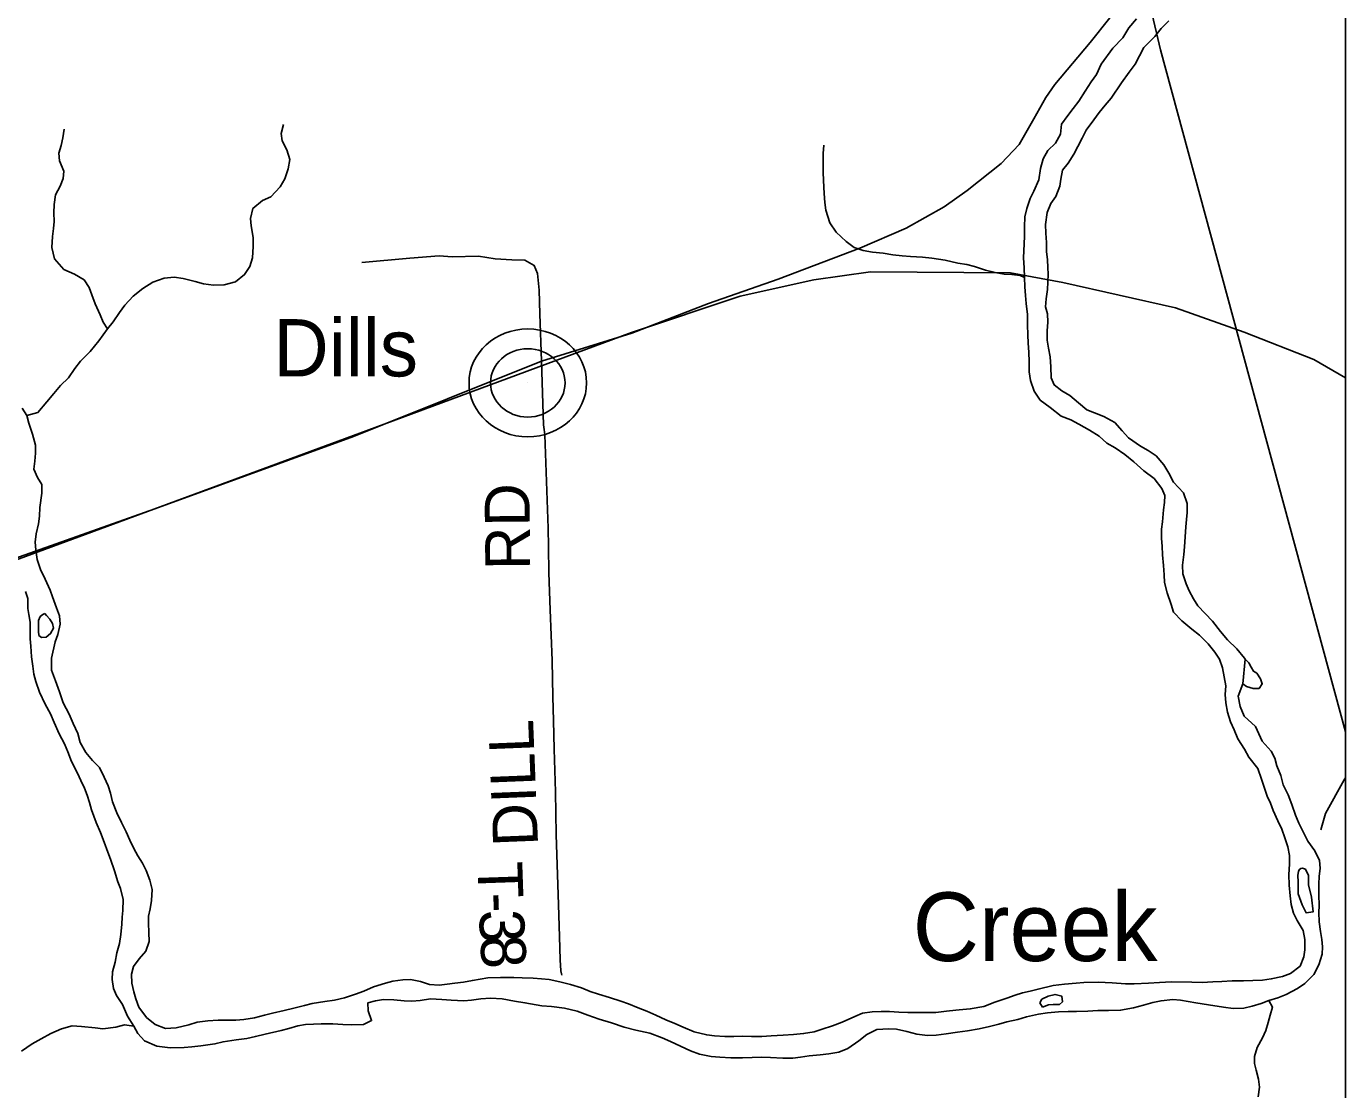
# Model space of a CAD drawing. Extents: x -139 to 835, y 0 to 440.
# Drawn here: x 550 to 607.6, y 298.1 to 344.5 of the extents above; entities that cross this region are included whole.
import ezdxf

# ---------------------------------------------------------------- set-up
doc = ezdxf.new("R2010")
doc.units = 0
for name, color, linetype in [('Default', 7, 'Continuous'), ('GM_X_Major_River', 7, 'Continuous'), ('GM_X_Major_River_Text', 7, 'Continuous'), ('GM_X_Minor_River', 7, 'Continuous'), ('GM_X_Rail_Line', 7, 'Continuous'), ('GM_X_Township_Road', 7, 'Continuous'), ('GM_X_Township_Road_Text', 7, 'Continuous'), ('GM_X_Unincorporated', 7, 'Continuous'), ('GM_X_Unincorporated_Location', 7, 'Continuous'), ('GM_X_Unincorporated_Text', 7, 'Continuous'), ('GM_X_US_Route', 7, 'Continuous'), ('SH_Cut_Line', 7, 'Continuous')]:
    doc.layers.add(name, color=color, linetype=linetype)

msp = doc.modelspace()

# ---------------------------------------------------------------- linework, layer by layer
at = {"layer": 'Default'}
msp.add_lwpolyline([(607.596, 313.688), (607.596, 400.079), (567.097, 400.079), (573.292, 389.29), (593.771, 354.537), (598.348, 346.669), (599.103, 345.232), (599.523, 343.435)], close=True, dxfattribs=at)
msp.add_lwpolyline([(533.705, 218.461), (553.865, 217.083), (607.596, 213.413), (607.596, 313.688), (599.523, 343.435), (599.103, 345.232), (598.348, 346.669), (593.771, 354.537), (573.292, 389.29), (556.01, 382.105), (544.238, 377.806)], dxfattribs=at)
at = {"layer": 'GM_X_Major_River'}
msp.add_line((603.215, 316.859), (603.108, 315.776), dxfattribs=at)
for points in [[(597.447, 343.518), (597.884, 343.969), (598.138, 344.398), (598.47, 344.801)], [(598.791, 343.538), (599.267, 344.024), (599.546, 344.369), (599.877, 344.7)], [(597.447, 343.518), (596.939, 342.813), (596.725, 342.372), (596.499, 342.05), (596.233, 341.633), (595.954, 341.204), (595.716, 340.883), (595.477, 340.574), (595.198, 340.193), (595.154, 339.761), (594.94, 339.368), (594.61, 339.047), (594.397, 338.69), (594.287, 338.259), (594.216, 337.768), (594.001, 337.279), (593.841, 336.956), (593.692, 336.514), (593.609, 336.155), (593.59, 335.723), (593.585, 335.292), (593.564, 334.668), (593.547, 334.368), (593.567, 333.924), (593.588, 333.504), (593.596, 333.096), (593.63, 332.724), (593.665, 332.375), (593.711, 331.895), (593.718, 331.439), (593.738, 331.007), (593.747, 330.647), (593.781, 330.251), (593.788, 329.831), (593.796, 329.399), (593.856, 329.014), (594.006, 328.545), (594.275, 328.158), (594.701, 327.83), (595.191, 327.452), (595.606, 327.292), (595.956, 327.108), (596.422, 326.851), (596.848, 326.583), (597.183, 326.279), (597.546, 326.083), (597.959, 325.791), (598.359, 325.463), (598.797, 325.074), (599.249, 324.733), (599.582, 324.298), (599.708, 323.997), (599.691, 323.697), (599.648, 323.373), (599.602, 322.846), (599.559, 322.523), (599.567, 322.127), (599.589, 321.791), (599.61, 321.406), (599.656, 320.938), (599.677, 320.542), (599.699, 320.194), (599.81, 319.749), (599.986, 319.243), (600.086, 318.906), (600.446, 318.53), (600.885, 318.166), (601.22, 317.898), (601.606, 317.522), (601.888, 317.159), (602.093, 316.857), (602.231, 316.472), (602.305, 316.087), (602.365, 315.69), (602.347, 315.307), (602.368, 314.947), (602.441, 314.538), (602.579, 314.117), (602.731, 313.767), (602.895, 313.381), (603.189, 312.934), (603.38, 312.584), (603.765, 312.088), (603.928, 311.619), (604.041, 311.27), (604.18, 310.872), (604.319, 310.571), (604.432, 310.258), (604.635, 309.8), (604.813, 309.438), (604.951, 309.053), (605.077, 308.667), (605.15, 308.283), (605.145, 307.911), (605.126, 307.467), (605.133, 306.999), (605.18, 306.531), (605.227, 306.158), (605.326, 305.773), (605.478, 305.46), (605.746, 305.013)], [(598.791, 343.538), (598.412, 342.822), (598.16, 342.464), (597.815, 342), (597.363, 341.333), (597.112, 341.024), (596.847, 340.703), (596.609, 340.394), (596.277, 339.941), (596.103, 339.583), (595.916, 339.225), (595.742, 338.891), (595.489, 338.498), (595.251, 338.189), (595.168, 337.794), (595.125, 337.494), (594.95, 337.04), (594.737, 336.731), (594.576, 336.349), (594.504, 335.822), (594.512, 335.438), (594.546, 335.029), (594.554, 334.645), (594.588, 334.285), (594.61, 333.949), (594.619, 333.649), (594.602, 333.301), (594.585, 332.989), (594.527, 332.582), (594.51, 332.222), (594.597, 331.922), (594.605, 331.562), (594.575, 331.178), (594.569, 330.77), (594.63, 330.422), (594.703, 330.049), (594.737, 329.617), (594.757, 329.125), (594.883, 328.823), (595.219, 328.556), (595.568, 328.36), (595.942, 328.044), (596.303, 327.74), (596.64, 327.605), (597.042, 327.444), (597.521, 327.187), (597.855, 326.824), (598.125, 326.509), (598.641, 326.144), (598.978, 325.96), (599.327, 325.728), (599.66, 325.341), (599.89, 324.978), (600.094, 324.58), (600.518, 324.12), (600.681, 323.65), (600.689, 323.254), (600.659, 322.955), (600.629, 322.631), (600.597, 322.188), (600.566, 321.756), (600.535, 321.42), (600.477, 320.953), (600.499, 320.581), (600.636, 320.148), (600.776, 319.834), (600.967, 319.484), (601.145, 319.183), (601.467, 318.855), (601.788, 318.516), (602.134, 318.056), (602.443, 317.705), (602.855, 317.305), (603.188, 316.905), (603.215, 316.859)], [(563.066, 301.923), (562.517, 301.833), (562.177, 301.741), (561.707, 301.626), (561.288, 301.523), (560.779, 301.408), (560.426, 301.316), (559.994, 301.213), (559.524, 301.134), (559.185, 301.102), (558.416, 301.11), (557.959, 301.079), (557.489, 301.012), (557.136, 300.896), (556.574, 300.77), (556.118, 300.739), (555.664, 300.912), (555.277, 301.228), (554.944, 301.676), (554.818, 302.037), (554.731, 302.338), (554.644, 302.722), (554.636, 303.106), (554.719, 303.453), (554.958, 303.787), (555.262, 304.119), (555.397, 304.538), (555.39, 304.934), (555.368, 305.33), (555.372, 305.642), (555.442, 305.965), (555.499, 306.324), (555.531, 306.804), (555.432, 307.213), (555.268, 307.634), (555.115, 307.948), (554.911, 308.274), (554.733, 308.588), (554.555, 308.962), (554.39, 309.323), (554.2, 309.733), (553.997, 310.155), (553.808, 310.637), (553.708, 311.01), (553.608, 311.323), (553.443, 311.709), (553.24, 312.131), (552.931, 312.435), (552.636, 312.786), (552.394, 313.22), (552.282, 313.617), (552.079, 314.051), (551.915, 314.461), (551.648, 314.956), (551.484, 315.425), (551.308, 315.907), (551.145, 316.377), (551.138, 316.893), (551.304, 317.611), (551.412, 317.933), (551.522, 318.376), (551.488, 318.748), (551.362, 319.098), (551.185, 319.568), (551.085, 319.869), (550.87, 320.351), (550.666, 320.761), (550.516, 321.206), (550.456, 321.627), (550.421, 321.963), (550.478, 322.322), (550.575, 322.765), (550.618, 323.101), (550.636, 323.472), (550.722, 324.095), (550.714, 324.479), (550.536, 324.781), (550.371, 325.143), (550.414, 325.49), (550.445, 325.838), (550.436, 326.198), (550.312, 326.667), (550.149, 327.149), (550.062, 327.486), (549.858, 327.812)], [(575.564, 300.984), (575.032, 301.146), (574.539, 301.319), (574.072, 301.492), (573.514, 301.63), (572.954, 301.696), (572.525, 301.737), (571.796, 301.865), (571.341, 301.929), (570.795, 302.031), (570.287, 302.061), (569.87, 302.029), (569.465, 301.974), (569.126, 301.954), (568.579, 301.971), (568.162, 302.012), (567.68, 302.029), (567.224, 301.962), (566.858, 301.93), (566.52, 301.946), (566.077, 301.987), (565.621, 302.004), (565.269, 301.947), (564.942, 301.855), (564.95, 301.507), (565.101, 301.085), (564.747, 300.909), (564.226, 300.903), (563.848, 300.919), (563.418, 300.948), (562.91, 300.941), (562.571, 300.933), (562.219, 300.913), (561.892, 300.856), (561.487, 300.741), (561.16, 300.648), (560.454, 300.488), (560.036, 300.397), (559.657, 300.305), (559.2, 300.25), (558.625, 300.16), (558.272, 300.068), (557.659, 299.99), (557.267, 299.935), (556.928, 299.914), (556.315, 299.897), (555.73, 299.975), (555.198, 300.197), (554.903, 300.524), (554.737, 300.838), (554.456, 301.285), (554.241, 301.791), (553.973, 302.178), (553.846, 302.491), (553.786, 302.876), (553.804, 303.211), (553.913, 303.63), (553.997, 304.037), (554.106, 304.444), (554.163, 304.839), (554.208, 305.295), (554.225, 305.594), (554.255, 305.894), (554.261, 306.374), (554.15, 306.843), (554.036, 307.144), (553.886, 307.625), (553.71, 308.131), (553.597, 308.432), (553.433, 308.866), (553.282, 309.288), (553.092, 309.733), (552.891, 310.287), (552.791, 310.6), (552.691, 310.926), (552.577, 311.227), (552.425, 311.564), (552.273, 311.878), (552.019, 312.396), (551.855, 312.818), (551.703, 313.168), (551.474, 313.602), (551.259, 314.096), (551.094, 314.47), (550.865, 314.892), (550.611, 315.411), (550.461, 315.88), (550.373, 316.205), (550.326, 316.554), (550.266, 316.962), (550.233, 317.418), (550.211, 317.743), (550.216, 318.174), (550.207, 318.474), (550.146, 318.811), (550.11, 319.063), (550.103, 319.507), (550.003, 319.808)], [(550.85, 318.851), (550.759, 318.804), (550.64, 318.71), (550.573, 318.542), (550.57, 318.303), (550.567, 318.075), (550.591, 317.894), (550.707, 317.797), (550.902, 317.819), (551.1, 317.973), (551.22, 318.211), (551.184, 318.416), (551.069, 318.597), (550.915, 318.767)], [(550.915, 318.767), (550.85, 318.851)], [(603.108, 315.776), (603.277, 315.669), (603.562, 315.582), (603.823, 315.579), (603.956, 315.781), (603.88, 315.998), (603.727, 316.24), (603.572, 316.325), (603.483, 316.506), (603.381, 316.699), (603.215, 316.859)], [(603.108, 315.776), (602.906, 315.241), (602.992, 314.784), (603.169, 314.362), (603.658, 313.913), (603.81, 313.599), (603.95, 313.274), (604.348, 312.838), (604.501, 312.536), (604.601, 312.199), (604.765, 311.778), (604.877, 311.369), (605.093, 310.934), (605.257, 310.513), (605.407, 310.055), (605.559, 309.706), (605.737, 309.344), (605.953, 308.91), (606.26, 308.487), (606.45, 308.065), (606.485, 307.74), (606.441, 307.369), (606.424, 307.057), (606.431, 306.577), (606.438, 306.109), (606.434, 305.798), (606.442, 305.402), (606.502, 304.969), (606.562, 304.621), (606.585, 304.308), (606.58, 303.985), (606.431, 303.518), (606.204, 303.101), (605.821, 302.709), (605.493, 302.485), (605.007, 302.226), (604.64, 302.074), (604.248, 301.958), (603.907, 301.83), (603.515, 301.714), (603.149, 301.634), (602.692, 301.615), (602.263, 301.668), (601.613, 301.77), (601.067, 301.86), (600.39, 301.976), (600.052, 302.003), (599.543, 301.949), (599.19, 301.869), (598.772, 301.753), (598.34, 301.638), (597.778, 301.536), (597.257, 301.529), (596.788, 301.522), (596.344, 301.503), (595.849, 301.485), (595.497, 301.476), (595.067, 301.469), (594.597, 301.426), (594.205, 301.37), (593.67, 301.256), (593.303, 301.14), (592.819, 301.025), (592.466, 300.933), (592.061, 300.83), (591.604, 300.727), (591.094, 300.636), (590.664, 300.581), (590.167, 300.502), (589.737, 300.447), (589.358, 300.439), (588.89, 300.492), (588.448, 300.617), (588.007, 300.705), (587.668, 300.733), (587.146, 300.691), (586.713, 300.479), (586.358, 300.207), (585.885, 299.865), (585.492, 299.713), (585.047, 299.634), (584.669, 299.59), (584.199, 299.547), (583.808, 299.491), (583.481, 299.447), (583.051, 299.451), (582.504, 299.481), (582.1, 299.486), (581.709, 299.478), (581.292, 299.458), (580.771, 299.464), (580.302, 299.493), (579.911, 299.521), (579.405, 299.623), (579.015, 299.771), (578.147, 300.176), (577.785, 300.336), (577.24, 300.534), (576.629, 300.673), (576.122, 300.798), (575.564, 300.984)], [(605.545, 307.607), (605.517, 307.415), (605.526, 307.139), (605.532, 306.611), (605.696, 306.141), (605.874, 305.792), (606.187, 305.836), (606.104, 306.473), (605.981, 307.014), (605.973, 307.422), (605.846, 307.699)], [(605.846, 307.699), (605.712, 307.734), (605.637, 307.72), (605.586, 307.684), (605.545, 307.607)], [(605.746, 305.013), (605.82, 304.617), (605.814, 304.173), (605.771, 303.873), (605.609, 303.467), (605.188, 303.136), (604.848, 303.007), (604.351, 302.905), (603.972, 302.849), (603.555, 302.829), (603.138, 302.822), (602.643, 302.815), (602.199, 302.796), (601.808, 302.776), (601.339, 302.745), (600.883, 302.762), (599.997, 302.772), (599.475, 302.741), (598.992, 302.722), (598.367, 302.693), (597.989, 302.697), (597.416, 302.727), (596.804, 302.758), (596.178, 302.741), (595.839, 302.72), (595.33, 302.678), (594.834, 302.611), (594.18, 302.462), (593.84, 302.37), (593.5, 302.29), (593.173, 302.197), (592.82, 302.069), (592.296, 301.883), (591.812, 301.708), (591.224, 301.594), (590.741, 301.552), (590.585, 301.541), (590.18, 301.498), (589.723, 301.443), (589.319, 301.435), (588.498, 301.444), (588.107, 301.46), (587.691, 301.477), (587.339, 301.48), (586.948, 301.473), (586.517, 301.405), (586.189, 301.265), (585.639, 301.019), (585.207, 300.856), (584.762, 300.705), (584.408, 300.6), (583.951, 300.521), (583.508, 300.478), (583.064, 300.447), (582.529, 300.417), (582.125, 300.385), (581.682, 300.39), (581.278, 300.406), (580.9, 300.386), (580.509, 300.391), (580.066, 300.419), (579.728, 300.459), (579.182, 300.597), (578.69, 300.794), (578.327, 300.954), (577.938, 301.126), (577.511, 301.323), (577.109, 301.495), (576.733, 301.643), (576.318, 301.816), (575.981, 301.939), (575.487, 302.088), (575.007, 302.238), (574.644, 302.362), (574.268, 302.51), (573.787, 302.659), (573.32, 302.772), (572.852, 302.873), (572.514, 302.912), (572.149, 302.94), (571.68, 302.958), (571.315, 302.973), (570.729, 302.968), (570.168, 302.95), (569.502, 302.837), (569.11, 302.769), (568.732, 302.714), (568.405, 302.669), (568.053, 302.637), (567.636, 302.665), (567.234, 302.79), (566.805, 302.878), (566.466, 302.87), (566.035, 302.803), (565.709, 302.722), (565.185, 302.56), (564.766, 302.373), (564.399, 302.245), (563.928, 302.082), (563.483, 301.979), (563.066, 301.923)], [(594.366, 301.669), (594.628, 301.774), (594.836, 301.783), (595.11, 301.792), (595.242, 301.911), (595.219, 302.151), (594.92, 302.226), (594.619, 302.146), (594.344, 302.017), (594.251, 301.862)], [(594.251, 301.862), (594.366, 301.669)]]:
    msp.add_lwpolyline(points, dxfattribs=at)
at = {"layer": 'GM_X_Minor_River'}
for points in [[(550.062, 327.486), (550.546, 327.624), (550.943, 328.076), (551.247, 328.445), (551.539, 328.801), (551.882, 329.133), (552.16, 329.538), (552.412, 329.859), (552.821, 330.275), (553.206, 330.751), (553.59, 331.262), (553.829, 331.572), (554.107, 331.976), (554.346, 332.298), (554.703, 332.69), (555.124, 333.033), (555.558, 333.304), (556.055, 333.479), (556.486, 333.522), (556.889, 333.458), (557.409, 333.332), (557.772, 333.232), (558.202, 333.168), (558.671, 333.187), (559.168, 333.313), (559.563, 333.633), (559.789, 333.99), (559.911, 334.373), (559.944, 334.864), (559.936, 335.248), (559.851, 335.765), (559.816, 336.089), (559.926, 336.52), (560.347, 336.863), (560.714, 337.027), (561.111, 337.467), (561.324, 337.813), (561.46, 338.255), (561.53, 338.65), (561.405, 339.083), (561.202, 339.469), (561.154, 339.794), (561.263, 340.189)], [(553.59, 331.262), (553.398, 331.564), (553.259, 331.878), (553.044, 332.36), (552.905, 332.745), (552.779, 333.071), (552.562, 333.409), (552.148, 333.653), (551.682, 333.862), (551.271, 334.323), (551.16, 334.816), (551.179, 335.295), (551.222, 335.643), (551.252, 335.954), (551.244, 336.326), (551.249, 336.698), (551.319, 337.117), (551.52, 337.499), (551.654, 337.822), (551.671, 338.145), (551.495, 338.603), (551.46, 338.927), (551.556, 339.274), (551.638, 339.609), (551.695, 339.981)], [(593.588, 333.504), (593.394, 333.602), (593.042, 333.642), (592.704, 333.658), (592.314, 333.722), (591.885, 333.822), (591.405, 333.983), (591.067, 334.071), (590.677, 334.135), (590.131, 334.261), (589.546, 334.352), (589.142, 334.392), (588.621, 334.422), (588.257, 334.449), (587.841, 334.502), (587.424, 334.566), (586.956, 334.619), (586.553, 334.684), (586.15, 334.82), (585.802, 335.076), (585.364, 335.488), (585.096, 335.899), (584.92, 336.441), (584.872, 336.777), (584.851, 337.174), (584.819, 337.738), (584.811, 338.098), (584.804, 338.59), (584.809, 338.914), (584.826, 339.285)], [(604.248, 301.958), (604.4, 301.669), (604.305, 301.322), (604.222, 300.999), (604.114, 300.652), (603.966, 300.33), (603.739, 299.912), (603.617, 299.518), (603.626, 299.218), (603.701, 298.917), (603.8, 298.532), (603.834, 298.184), (603.777, 297.764)], [(554.737, 300.838), (554.321, 300.902), (553.942, 300.799), (553.381, 300.733), (553.042, 300.772), (552.444, 300.827), (552.04, 300.855), (551.569, 300.728), (551.111, 300.529), (550.691, 300.294), (550.297, 300.07), (549.824, 299.752)]]:
    msp.add_lwpolyline(points, dxfattribs=at)
at = {"layer": 'GM_X_Rail_Line'}
msp.add_lwpolyline([(510.606, 306.801), (564.86, 326.817), (576.442, 331.103), (581.189, 332.695), (584.393, 333.405), (586.87, 333.757), (592.97, 333.71), (595.263, 333.287), (600.181, 332.19), (603.167, 331.128), (606.212, 329.926), (607.596, 329.125)], dxfattribs=at)
at = {"layer": 'GM_X_Township_Road'}
for points in [[(568.053, 334.453), (566.769, 334.346), (564.673, 334.166)], [(572.411, 332.956), (572.407, 333.108), (572.344, 333.686), (572.201, 334.034), (571.79, 334.257), (571.229, 334.274), (570.501, 334.326), (569.764, 334.44), (568.614, 334.413), (568.053, 334.453)], [(572.518, 329.858), (572.444, 331.925), (572.411, 332.956)], [(572.816, 321.751), (572.801, 322.567), (572.668, 326.643), (572.638, 326.88), (572.609, 327.084), (572.518, 329.858)], [(573.408, 303.066), (573.392, 303.12), (573.362, 303.262), (573.325, 303.737), (573.303, 304.761), (573.257, 306.144), (573.155, 309.209), (573.126, 311.06), (573.074, 312.925), (573.045, 314.173), (573.015, 315.21), (572.985, 316.804), (572.889, 319.001), (572.838, 320.621), (572.816, 321.751)], [(606.516, 309.414), (606.723, 310.117), (607.531, 311.584), (607.596, 311.673)]]:
    msp.add_lwpolyline(points, dxfattribs=at)
at = {"layer": 'GM_X_Unincorporated'}
for major_axis in [(2.564, 0), (1.625, 0)]:
    msp.add_ellipse((571.918, 328.911), major_axis=major_axis, ratio=0.917426, dxfattribs=at)
at = {"layer": 'GM_X_Unincorporated_Location'}
msp.add_line((571.918, 328.911), (571.918, 328.911), dxfattribs=at)
at = {"layer": 'GM_X_US_Route'}
msp.add_lwpolyline([(549.297, 321.159), (555.655, 323.421), (564.321, 326.564), (572.518, 329.858), (576.454, 331.078), (579.806, 332.38), (582.837, 333.43), (586.404, 334.793), (588.425, 335.666), (590.09, 336.591), (591.084, 337.301), (592.564, 338.477), (593.36, 339.308), (593.991, 340.424), (594.511, 341.356), (594.906, 341.923), (596.447, 343.761), (597.314, 344.835), (597.721, 345.502), (598.356, 346.652), (598.705, 347.289), (598.938, 347.509)], dxfattribs=at)
at = {"layer": 'SH_Cut_Line'}
msp.add_lwpolyline([(607.596, 213.413), (607.596, 400.079), (373.24, 400.079), (373.24, 228.621), (390.412, 227.867), (402.968, 227.036), (407.389, 226.858), (433.728, 225.419), (479.461, 222.215), (494.743, 221.147), (512.652, 220.106), (533.705, 218.461), (553.865, 217.083)], close=True, dxfattribs=at)

# ---------------------------------------------------------------- texts
at = {"layer": 'GM_X_Major_River_Text'}
msp.add_text('Creek', height=2.9941, rotation=0.00292, dxfattribs=at).set_placement((588.711, 303.684))
at = {"layer": 'GM_X_Township_Road_Text'}
for s, height, rotation, p in [('RD', 1.9582, 90.53808, (572.024, 320.757)), ('DILL', 1.9584, 92.29967, (572.369, 308.722)), ('T', 1.958, 271.98547, (569.717, 307.99)), ('-', 1.958, 272.02548, (569.764, 306.645)), ('3', 1.958, 272.3195, (569.79, 305.899)), ('8', 1.959, 273.34078, (569.836, 304.761))]:
    msp.add_text(s, height=height, rotation=rotation, dxfattribs=at).set_placement(p)
at = {"layer": 'GM_X_Unincorporated_Text'}
msp.add_text('Dills', height=2.4971, rotation=0.00001, dxfattribs=at).set_placement((560.822, 329.193))

doc.saveas('drawing.dxf')
